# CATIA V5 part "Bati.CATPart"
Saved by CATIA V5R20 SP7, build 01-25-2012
Part number: Bati
Bounding box of the stored display mesh (mm): x -55 to 55, y -54.987 to 54.987, z -147 to 105
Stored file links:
  F:\Travaux\Modélisations\CFAO_2011\MMS\MMS_GR1\AA_OK\bmadec\Catia\Bati.CATPart
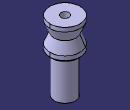
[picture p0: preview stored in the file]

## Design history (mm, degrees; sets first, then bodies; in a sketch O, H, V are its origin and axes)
Body1 (main body)
  Sketch1 on xy-plane, origin (0, 0, 0), H (1, 0, 0), V (0, 1, 0)
    circle A1 centre (0, 0) radius 55
    radius A1 = 55
  Pad1: profile Sketch1, direction (0, 0, 1), length 105
  Sketch2 on yz-plane, origin (0, 0, 0), H (0, 1, 0), V (0, 0, 1)
    point P1 (55, 90)
    line L1 (55, 90) -> (40, 52.5)
    point P2 (40, 52.5)
    line L2 (40, 52.5) -> (55, 15)
    point P3 (55, 15)
    line L3 (55, 15) -> (55, 90)
    reference projected line E1 (-55, 105) -> (55, 105) from edge [face of Pad1 from Sketch1.A1 | end face of Pad1]
    reference projected line E2 (-55, 0) -> (55, 0) from edge [start face of Pad1 | face of Pad1 from Sketch1.A1]
    reference projected line E3 through (0, 0) direction (0, 1) from axis of face of Pad1 from Sketch1.A1
    reference projected line E4 through (0, 0) direction (0, 1) from axis of face of Pad1 from Sketch1.A1
    distance P1 E1 = 15
    distance P3 E2 = 15
    distance P2 E3 = 40
    distance L3 E4 = 55
    vertical: L3 V
    equidistance: P3 P1 P2
  Groove1: profile Sketch2, axis axis of face of Pad1 from Sketch1.A1, angle 360
  Sketch3 on end face of Pad1, origin (0, 0, 105), H (1, 0, 0), V (0, 1, 0)
    point P1 (0, 0)
    coincidence: P1 O
  Hole1: placed by Sketch3, at (0, 0, 105) direction (0, 0, -1), diameter 30, through (limit type 6)
  Sketch4 on start face of Pad1, origin (0, 0, 0), H (1, 0, 0), V (0, -1, 0)
    circle A1 centre (0, 0) radius 50
    radius A1 = 50
  Pad2: profile Sketch4, direction (0, 0, -1), length 6
  Sketch5 on end face of Pad2, origin (0, 0, -6), H (1, 0, 0), V (0, -1, 0)
    point P1 (0, 0)
    coincidence: P1 O
  Hole2: placed by Sketch5, at (0, 0, -6) direction (0, 0, 1), diameter 6, through (limit type 6)
  Sketch6 on yz-plane, origin (0, 0, 0), H (0, 1, 0), V (0, 0, 1)
    line L1 (37.5, -6) -> (37.5, -147)
    line L2 (37.5, -147) -> (31.5, -147)
    line L3 (31.5, -147) -> (31.5, -127)
    line L4 (31.5, -127) -> (34.5, -127)
    line L5 (34.5, -127) -> (34.5, -6)
    line L6 (34.5, -6) -> (37.5, -6)
    reference projected line E1 (50, -6) -> (-50, -6) from edge [face of Pad2 from Sketch4.A1 | end face of Pad2]
    reference projected line E2 through (0, 0) direction (0, 1) from axis of face of Pad1 from Sketch1.A1
    reference projected line E3 through (0, 0) direction (0, 1) from axis of face of Pad1 from Sketch1.A1
    distance L1 E2 = 37.5
    distance L5 E3 = 34.5
    length L2 = 6
    distance L3 L5 = 3 (reference)
    length L3 = 20
    length L1 = 141
    vertical: L1 V, L3 V, L5 V
    horizontal: L2 H, L4 H, L6 H
    coincidence: L6 E1
  Shaft1: profile Sketch6, axis axis of face of Pad1 from Sketch1.A1, angle 360
  Sketch7 on yz-plane, origin (0, 0, 0), H (0, 1, 0), V (0, 0, 1)
    line L1 (24.1513, -132) -> (35, -132)
    line L2 (35, -132) -> (35, -142)
    line L3 (35, -142) -> (24.1513, -142)
    line L4 (24.1513, -142) -> (24.1513, -132)
    reference projected line E1 through (0, 0) direction (0, 1) from axis of face of Shaft1 from Sketch6.L1
    reference projected line E2 (-37.5, -147) -> (37.5, -147) from edge [face of Shaft1 from Sketch6.L2 | face of Shaft1 from Sketch6.L1]
    length L2 = 10
    distance L2 E1 = 35
    distance L3 E2 = 5
    horizontal: L1 H, L3 H
    vertical: L2 V, L4 V
  Groove2: profile Sketch7, axis axis of face of Shaft1 from Sketch6.L1, angle 360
